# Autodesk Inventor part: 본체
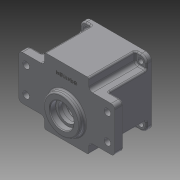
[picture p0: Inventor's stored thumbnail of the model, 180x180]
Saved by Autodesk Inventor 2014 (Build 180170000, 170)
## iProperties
Created: 2015-07
Part Number: 본체
Material: Generic
Document SubType Name: Modeling
Designer: Administrator
Density: 1 g/cm^3
Appearance: Default
Author: Administrator
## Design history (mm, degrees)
sketch "스케치1"
  geometry: L1 (45, 45)-(-45, 45); L2 (-45, 45)-(-45, -45); L3 (-45, -45)-(45, -45); L4 (45, -45)-(45, 45); L5 (45, 45)-(-45, -45); L6 (-45, 45)-(45, -45); 1 further point
  constraints: 12 end point, 2 midpoint, 2 parallel, 1 horizontal, 1 perpendicular
  dimensions: "d0" = 90 distance of L3.end L2.end; "d1" = 90 distance of L2.end L1.end
extrude "돌출1" new body sketch "스케치1" distance "d2" = 70; taper "d3" = 0 deg
sketch "스케치3"
  geometry: L1 (-65, 30)-(65, 30); L2 (65, 30)-(65, -30); L3 (65, -30)-(-65, -30); L4 (-65, -30)-(-65, 30); L5 (-65, 30)-(65, -30); L6 (65, 30)-(-65, -30); 1 further point
  constraints: 12 end point, 2 midpoint, 2 parallel, 1 horizontal, 1 perpendicular
  dimensions: "d8" = 130 distance of L2.end L3.end; "d9" = 60 distance of L1.end L2.end
extrude "돌출3" join sketch "스케치3" distance "d10" = 12; taper "d11" = 0 deg
sketch "스케치4"
  geometry: L1 (65, -30)-(45, -30) reference; L2 (45, 30)-(65, 30) reference; L3 (-65, 30)-(-45, 30) reference; L4 (-45, -30)-(-65, -30) reference; L5 (-45, 45)-(-30, 45); L6 (-30, 45)-(-30, 30); L7 (-30, 30)-(-45, 30); L8 (-45, 30)-(-45, 45); L9 (45, 45)-(30, 45); L10 (30, 45)-(30, 30); L11 (30, 30)-(45, 30); L12 (45, 30)-(45, 45); L13 (-45, -45)-(-30, -45); L14 (-30, -45)-(-30, -30); L15 (-30, -30)-(-45, -30); L16 (-45, -30)-(-45, -45); L17 (45, -45)-(30, -45); L18 (30, -45)-(30, -30); L19 (30, -30)-(45, -30); L20 (45, -30)-(45, -45); 1 further point
  constraints: 32 end point, 8 parallel, 4 horizontal, 4 perpendicular, 3 collinear, 1 point on line
  dimensions: "d12" = 60 distance between parallel lines of L18 L14; "d13" = 60 distance between parallel lines of L10 L6; "d14" = 30 distance from line of L14 point (0, 0); "d15" = 30 distance from line of L6 point (0, 0)
extrude "돌출4" cut sketch "스케치4" distance "d16" = 63; taper "d17" = 0 deg
fillet "모깎기1" dims "d18" = 5
fillet "모깎기2" dims "d19" = 8
fillet "모깎기3" dims "d20" = 5
sketch "스케치5"
  geometry: L1 (37, -45)-(-37, -45) reference; L2 (-45, -37)-(-45, 37) reference; L3 (-37, 45)-(37, 45) reference; L4 (45, 37)-(45, -37) reference; C1 r 3.5 at (37, 37); C2 r 3.5 at (-37, 37); C3 r 3.5 at (37, -37); C4 r 3.5 at (-37, -37); A1 r 8 centre (37, -37) between (37, -45) and (45, -37) reference; A2 r 8 centre (-37, -37) between (-45, -37) and (-37, -45) reference; A3 r 8 centre (-37, 37) between (-37, 45) and (-45, 37) reference; A4 r 8 centre (37, 37) between (45, 37) and (37, 45) reference; 1 further point
  constraints: 4 centre point, 4 coincident
  dimensions: "d21" = 7 diameter of C1; "d22" = 7 diameter of C2; "d23" = 7 diameter of C3; "d24" = 7 diameter of C4
extrude "돌출5" cut sketch "스케치5" stored distance "d25" = 63; taper "d26" = 0 deg
sketch "스케치6"
  geometry: C1 r 4.5 at (-55, 17.5); C2 r 4.5 at (-55, -17.5); C3 r 4.5 at (55, -17.5); C4 r 4.5 at (55, 17.5); 1 further point
  constraints: 4 centre point, 2 horizontal alignment, 2 vertical alignment
  dimensions: "d27" = 9 diameter of C1; "d28" = 9 diameter of C2; "d29" = 9 diameter of C3; "d30" = 9 diameter of C4; "d31" = 35 distance of C3.centre C4.centre; "d32" = 110 distance of C4.centre C1.centre; "d33" = 17.5 vertical distance of C4.centre point (0, 0); "d34" = 55 horizontal distance of point (0, 0) C2.centre
extrude "돌출6" cut sketch "스케치6" stored distance "d35" = 63; taper "d36" = 0 deg
sketch "스케치7"
  geometry: C1 r 40 at (0, 0); 1 further point
  constraints: 1 centre point, 1 coincident
  dimensions: "d37" = 80 diameter of C1
extrude "돌출7" cut sketch "스케치7" distance "d38" = 9; taper "d39" = 0 deg
sketch "스케치8"
  geometry: C1 r 40 at (0, 0) reference; C2 r 39 at (0, 0)
  constraints: 1 centre point, 1 coincident
  dimensions: "d40" = 78 diameter of C2
extrude "돌출8" cut sketch "스케치8" distance "d41" = 52; taper "d42" = 0 deg
sketch "스케치10"
  geometry: C1 r 39 at (0, 0) reference; C2 r 20.5 at (0, 11); C3 r 14 at (0, -20)
  constraints: 2 centre point, 2 vertical alignment
  dimensions: "d50" = 41 diameter of C2; "d51" = 11 distance of C1.centre C2.centre; "d52" = 28 diameter of C3; "d53" = 20 distance of C3.centre C1.centre
extrude "돌출9" join sketch "스케치10" distance "d54" = 7; taper "d55" = 0 deg
sketch "스케치11"
  geometry: C1 r 17.5 at (0, 11); A1 r 20.5 centre (0, 11) between (7.402, -8.117) and (-7.402, -8.117) reference; 1 further point
  constraints: 1 centre point, 1 coincident
  dimensions: "d56" = 35 diameter of C1
extrude "돌출10" cut sketch "스케치11" distance "d57" = 10; taper "d58" = 0 deg
sketch "스케치12"
  geometry: C1 r 17.5 at (0, -11) reference; C2 r 25 at (0, -11); 1 further point
  constraints: 1 centre point, 1 coincident
  dimensions: "d59" = 50 diameter of C2
extrude "돌출11" join sketch "스케치12" distance "d60" = 7; taper "d61" = 0 deg
sketch "스케치13"
  geometry: C1 r 25 at (0, 0) reference; C2 r 16 at (0, 0); 1 further point
  constraints: 1 centre point, 1 coincident
  dimensions: "d62" = 32 diameter of C2
extrude "돌출12" cut sketch "스케치13" distance "d63" = 8; taper "d64" = 0 deg
sketch "스케치14"
  geometry: C1 r 16 at (0, 0) reference; C2 r 12.5 at (0, 0); 1 further point
  constraints: 1 centre point, 1 coincident
  dimensions: "d65" = 25 diameter of C2
extrude "돌출13" cut sketch "스케치14" stored distance "d66" = 10; taper "d67" = 0 deg
sketch "스케치15"
  geometry: C1 r 11 at (0, -20); A1 r 14 centre (0, -20) between (-7.402, -8.117) and (7.402, -8.117) reference; 1 further point
  constraints: 1 centre point, 1 coincident
  dimensions: "d68" = 22 diameter of C1
extrude "돌출14" cut sketch "스케치15" distance "d69" = 7; taper "d70" = 0 deg
sketch "스케치16"
  geometry: C1 r 11 at (0, 0) reference; C2 r 9.5 at (0, 0); 1 further point
  constraints: 1 centre point, 1 coincident
  dimensions: "d71" = 19 diameter of C2
extrude "돌출15" cut sketch "스케치16" distance "d72" = 1; taper "d73" = 0 deg
sketch "스케치17"
  geometry: L1 (0, 0)-(35, 0); L2 (-27.577, -27.577)-(27.577, 27.577); L3 (-27.577, 27.577)-(27.577, -27.577); L4 (27.577, 27.577)-(24.749, 24.749); L5 (24.749, 30.406)-(21.92, 27.577); L6 (27.577, 21.92)-(30.406, 24.749); A1 r 39 centre (0, 0) between (-27.577, -27.577) and (27.577, 27.577) reference; A2 r 35 centre (0, 0) between (35, 0) and (24.749, 24.749); A3 r 4 centre (27.577, 27.577) between (30.406, 24.749) and (24.749, 30.406); A4 r 4 centre (24.749, 24.749) between (21.92, 27.577) and (27.577, 21.92); 1 further point
  constraints: 14 end point, 10 point on circle, 4 tangent, 3 centre point, 3 midpoint, 1 coincident, 1 horizontal, 1 parallel, 1 point on line
  dimensions: "d74" = 70 diameter of A2; "d75" = 45 deg angle of L1 L2; "d76" = 90 deg angle of L2 L3; "d77" = 4 radius of A4
extrude "돌출16" join sketch "스케치17" stored distance "d78" = 10; taper "d79" = 0 deg
sketch "스케치18"
  geometry: A1 r 4 centre (-24.749, -24.749) between (-21.92, -27.577) and (-27.577, -21.92) reference; A2 r 4 centre (-24.749, 24.749) between (-27.577, 21.92) and (-21.92, 27.577) reference; A3 r 4 centre (24.749, 24.749) between (21.92, 27.577) and (27.577, 21.92) reference; A4 r 4 centre (24.749, -24.749) between (27.577, -21.92) and (21.92, -27.577) reference
hole "구멍1" sketch "스케치18" at (-24.749, 24.749), (-24.749, -24.749), (24.749, -24.749), (24.749, 24.749) diameter "d83" = 3.459; stored, may be unused: countersink angle "d87" = 90 deg, drill point angle "d89" = 118 deg; dims "d84" = 12, "d85" = 4, "d86" = 2, "d88" = 15
sketch "스케치19"
  geometry: L1 (30, 45)-(-30, 45) reference; C1 r 25 at (0, -11) reference; 2 further points
  constraints: 1 vertical alignment, 1 other
  dimensions: "d90" = 15 distance from line of L1 point (0, 30)
feature "엠보싱1" sketch "스케치19" dims "d0" = 90, "d1" = 90, "d91" = 0.5, "d92" = 0
fillet "모깎기4" dims "d93" = 3.5
fillet "모깎기5" dims "d94" = 3
fillet "모깎기6" dims "d95" = 0.3
chamfer "모따기1" distance "d96" = 1; stored, may be unused: second distance "d97" = 2, angle "d98" = 45 deg
fillet "모깎기7" dims "d99" = 2
fillet "모깎기8" dims "d100" = 2
fillet "모깎기9" dims "d101" = 2
fillet "모깎기10" dims "d102" = 2
node "솔리드1"
pattern_circular "원형 패턴1" dims angle "d81" = 360 deg
node "투영된 루프1"
node "투영된 루프2"
